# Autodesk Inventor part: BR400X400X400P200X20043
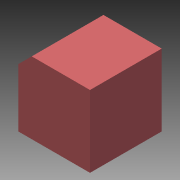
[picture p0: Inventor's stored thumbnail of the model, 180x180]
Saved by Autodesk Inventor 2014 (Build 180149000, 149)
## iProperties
Shininess: 64.0
Length Units: 11272
Angle Units: 11279
Time Units: 11290
Mass Units: 11286
Length Display Precision: 3
Angle Display Precision: 2
Compacted: True
Part Number: BR400X400X400P200X20043
Document SubType Name: Modeling
Created: 2003-04
Designer: t_enrig
Manufacturer: Standard
Standards Organization: Custom
Density: 1 g/cm^3
Mass: 1.03034 g
Surface Area: 6.04387 cm^2
Volume: 1.03034 cm^3
Material: Generic
Appearance: TranslatedColorStyle
Density: 0.0
Volumn: 0.0
Area: 0.0
PropertySet Name: Model Information
Control State: 0
Master: False
Checked Out: False
Author: t_enrig
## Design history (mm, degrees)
feature "Base1"
body "Solid1"
